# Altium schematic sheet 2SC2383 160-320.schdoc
size 127 x 101 mm
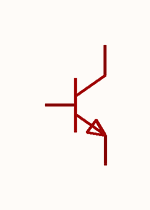
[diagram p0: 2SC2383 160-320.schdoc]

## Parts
Q?  2sc2383(range:160-320)_c24277  [SOT-89-3_L4.5-W2.5-P1.50-LS4.2-BR]  (value not drawn)

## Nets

Not connected (* = marked no-connect by the designer): Q? 1(B) 2(C) 3(E)

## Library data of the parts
Q? = 2sc2383(range:160-320)_c24277: 晶体管类型:NPN;集电极电流(Ic):1A;集射极击穿电压(Vceo):160V;耗散功率(Pd):500mW;直流电流增益(hFE):160;; Manufacturer: CJ(江苏长电/长晶); Symbol: 2SC2383 160-320; AddInBom: yes; ModelId: 6db690b7897d4d18a30d90c1b89525ee; ModelName: SOT-89-3_L4.3-W2.5-H1.6-LS4.1-P1.50; ModelTransform: 161.417,169.291,0,180,0,0,-18.661,0,0; type: NPN; Current - Collector(Ic): 1A; Collector - Emitter Voltage VCEO: 160V; Pd - Power Dissipation: 500mW; DC Current Gain: 160; Transition frequency(fT): 20MHz; Current - Collector Cutoff: 1uA; Vce Saturation(VCE(sat)): 1V; Emitter-Base Voltage(Vebo): 6V; Number: 1个NPN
